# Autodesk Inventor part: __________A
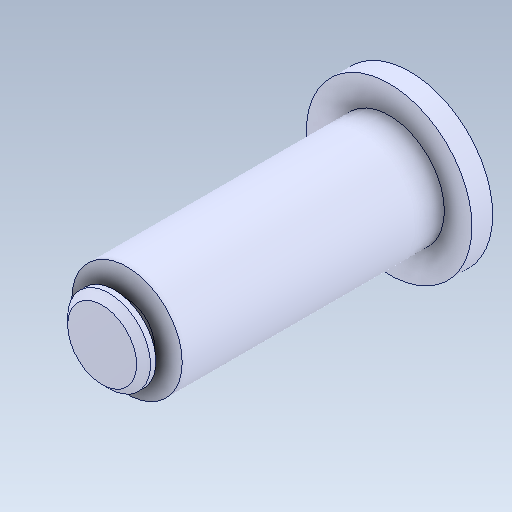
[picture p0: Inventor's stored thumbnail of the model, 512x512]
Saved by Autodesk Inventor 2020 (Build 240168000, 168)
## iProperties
Created: 2017-09
Part Number: __________A
Material: Générique
Document SubType Name: Modeling
Designer: bruno
Density: 1 g/cm^3
Appearance: Par défaut
Mass: 1.15922 g
Surface Area: 8.14109 cm^2
Volume: 1.15922 cm^3
Sending System: SolidWorks 2016
Author: bruno
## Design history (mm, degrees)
feature "Importée1"
node "Solide1"
